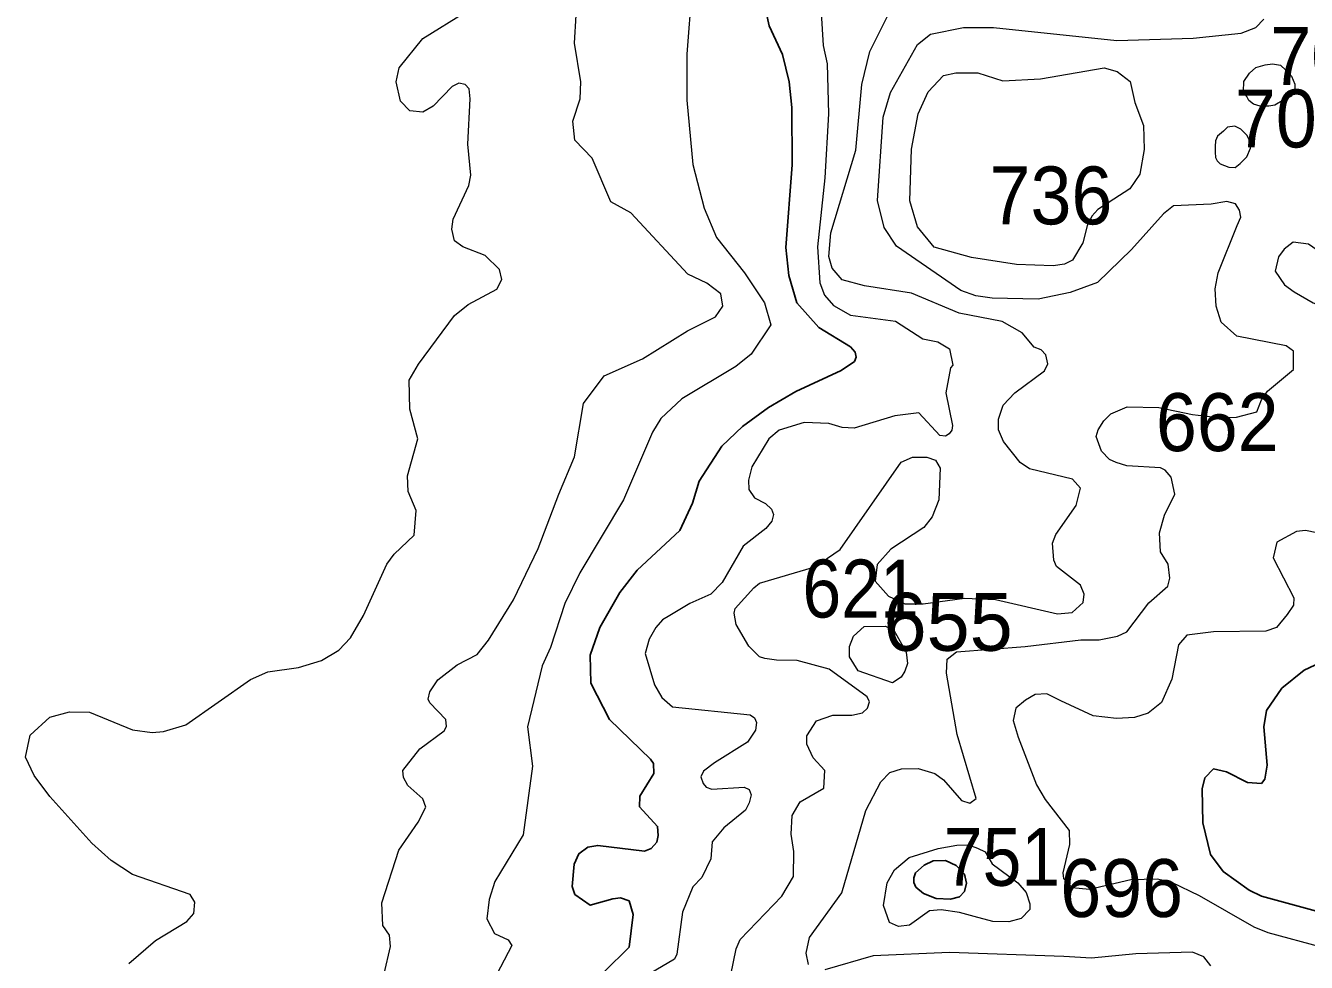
# Model space of a CAD drawing. Extents: x 499.9 to 555.3, y 9281.5 to 9336.8.
# Drawn here: x 537.076 to 540.616, y 9287.136 to 9289.724 of the extents above; entities that cross this region are included whole.
import ezdxf

# ---------------------------------------------------------------- set-up
doc = ezdxf.new("R2010")
doc.units = 0
doc.header["$LTSCALE"] = 0.064
doc.layers.add('1', color=7, linetype='Continuous', lineweight=25)
doc.layers.add('2', color=7, linetype='Continuous', lineweight=13)
doc.layers.add('21', color=7, linetype='Continuous')

msp = doc.modelspace()

# ---------------------------------------------------------------- linework, layer by layer
at = {"layer": '1'}
for points in [[(539.1142, 9289.7992), (539.1309, 9289.7229), (539.1682, 9289.6435), (539.1868, 9289.5684), (539.1943, 9289.4975), (539.1947, 9289.3393), (539.1773, 9289.1109), (539.1854, 9289.0337), (539.2081, 9288.9575), (539.2687, 9288.8893), (539.3559, 9288.836), (539.3689, 9288.8216), (539.3713, 9288.8081), (539.3673, 9288.7959), (539.3299, 9288.7704), (539.2048, 9288.7125), (539.1295, 9288.6684), (539.0579, 9288.6159), (539.0006, 9288.5618), (538.9382, 9288.4655), (538.9193, 9288.4043), (538.8846, 9288.3287), (538.7661, 9288.2189), (538.7189, 9288.1575), (538.6636, 9288.0612), (538.6362, 9287.9841), (538.6381, 9287.907), (538.6899, 9287.8065), (538.8029, 9287.6974), (538.8118, 9287.6849), (538.8123, 9287.6579), (538.7735, 9287.5947), (538.773, 9287.5656), (538.8227, 9287.5111), (538.824, 9287.4858), (538.8205, 9287.4677), (538.8047, 9287.4503), (538.7863, 9287.4433), (538.6576, 9287.4586), (538.6298, 9287.4538), (538.6056, 9287.4359), (538.5926, 9287.4069), (538.5869, 9287.3451), (538.5942, 9287.3234), (538.637, 9287.2937), (538.6992, 9287.3116), (538.72, 9287.3144), (538.7439, 9287.3055), (538.7552, 9287.2678), (538.744, 9287.1773), (538.6749, 9287.1093)], [(540.6821, 9287.9773), (540.6097, 9287.9425), (540.5477, 9287.8931), (540.5059, 9287.8314), (540.4983, 9287.7865), (540.5078, 9287.6809), (540.5007, 9287.6417), (540.4914, 9287.6298), (540.4529, 9287.6328), (540.3947, 9287.6624), (540.359, 9287.6701), (540.3351, 9287.6454), (540.328, 9287.6155), (540.3295, 9287.5209), (540.3512, 9287.4333), (540.3863, 9287.3863), (540.4577, 9287.3353), (540.4919, 9287.3189), (540.7655, 9287.2438)]]:
    msp.add_lwpolyline(points, dxfattribs=at)
msp.add_lwpolyline([(539.5366, 9287.3431), (539.5574, 9287.326), (539.593, 9287.3119), (539.6324, 9287.3104), (539.6576, 9287.3163), (539.671, 9287.3319), (539.6769, 9287.3542), (539.671, 9287.3794), (539.648, 9287.4032), (539.6183, 9287.4173), (539.5848, 9287.4158), (539.5596, 9287.404), (539.5358, 9287.3832), (539.5306, 9287.369), (539.5314, 9287.3564)], close=True, dxfattribs=at)
at = {"layer": '2'}
for points in [[(538.9179, 9289.8247), (538.9034, 9289.6449), (538.9035, 9289.5176), (538.9199, 9289.34), (538.9513, 9289.2192), (538.9855, 9289.138), (539.0631, 9289.0403), (539.1179, 9288.9581), (539.1357, 9288.8967), (539.0813, 9288.8163), (539.0388, 9288.7821), (538.8898, 9288.6927), (538.8319, 9288.6381), (538.8092, 9288.6009), (538.7283, 9288.4139), (538.6084, 9288.2117), (538.5661, 9288.1273), (538.5267, 9288.0057), (538.5038, 9287.9547), (538.4631, 9287.7868), (538.4769, 9287.6775), (538.4516, 9287.4883), (538.3727, 9287.3587), (538.357, 9287.309), (538.3512, 9287.2564), (538.3721, 9287.2155), (538.4098, 9287.1977), (538.4205, 9287.1826), (538.3365, 9287.022)], [(539.2717, 9289.8054), (539.2806, 9289.6687), (539.2918, 9289.6184), (539.2949, 9289.4801), (539.2855, 9289.3027), (539.2645, 9289.1126), (539.2715, 9289.0133), (539.2841, 9288.979), (539.3091, 9288.9505), (539.3562, 9288.9236), (539.4803, 9288.9067), (539.5559, 9288.8582), (539.5974, 9288.8497), (539.63, 9288.8311), (539.6387, 9288.786), (539.6321, 9288.7784), (539.6197, 9288.7089), (539.6381, 9288.6193), (539.6359, 9288.6064), (539.6289, 9288.5957), (539.6182, 9288.5893), (539.6033, 9288.591), (539.5445, 9288.654), (539.4781, 9288.6457), (539.3665, 9288.6112), (539.3325, 9288.613), (539.2965, 9288.624), (539.2281, 9288.6269), (539.1592, 9288.6059), (539.1301, 9288.5823), (539.0829, 9288.5044), (539.0739, 9288.468), (539.0754, 9288.4416), (539.0906, 9288.4187), (539.1212, 9288.4031), (539.1377, 9288.3873), (539.143, 9288.3726), (539.1387, 9288.355), (539.1217, 9288.3347), (539.0591, 9288.2857), (539.0009, 9288.1853), (538.9704, 9288.1529), (538.9124, 9288.1267), (538.8564, 9288.0944), (538.8364, 9288.0816), (538.8181, 9288.0611), (538.7992, 9288.0289), (538.7881, 9287.9889), (538.8141, 9287.9027), (538.835, 9287.8672), (538.8642, 9287.8416), (539.0784, 9287.8194), (539.0907, 9287.8113), (539.0965, 9287.7987), (539.0938, 9287.7773), (539.0709, 9287.7444), (538.9805, 9287.6868), (538.9501, 9287.6639), (538.942, 9287.6487), (538.9484, 9287.6294)], [(538.1386, 9288.6641), (538.1364, 9288.744), (538.1622, 9288.7884), (538.2616, 9288.9224), (538.2997, 9288.9529), (538.3787, 9288.9956), (538.3923, 9289.0225), (538.3863, 9289.0496), (538.3463, 9289.0885), (538.2844, 9289.1126), (538.2618, 9289.129), (538.2543, 9289.1611), (538.2584, 9289.1892), (538.3014, 9289.2821), (538.3065, 9289.3107), (538.2987, 9289.3958), (538.3048, 9289.5215), (538.3018, 9289.5487), (538.2909, 9289.5611), (538.274, 9289.5648), (538.2553, 9289.5551), (538.2024, 9289.5008), (538.1738, 9289.4843), (538.1386, 9289.4885), (538.1128, 9289.5149), (538.1004, 9289.5681), (538.1084, 9289.607), (538.174, 9289.6882), (538.2931, 9289.7615)], [(538.0669, 9287.1041), (538.0852, 9287.1795), (538.0819, 9287.2105), (538.0633, 9287.2371), (538.0612, 9287.3002), (538.1077, 9287.4461), (538.1616, 9287.5226), (538.1822, 9287.5644), (538.174, 9287.5876), (538.1324, 9287.6241), (538.1209, 9287.646), (538.1193, 9287.6662), (538.1661, 9287.7257), (538.233, 9287.7754), (538.2394, 9287.7869), (538.2374, 9287.8069), (538.1939, 9287.8531), (538.1893, 9287.8629), (538.1939, 9287.883), (538.2158, 9287.9158), (538.269, 9287.9574), (538.3246, 9287.9863), (538.3559, 9288.0255), (538.4244, 9288.1369), (538.4925, 9288.2794), (538.5498, 9288.429), (538.5931, 9288.5324), (538.6181, 9288.6794), (538.6749, 9288.7561), (538.781, 9288.803), (538.9057, 9288.8804), (538.9829, 9288.9191), (539.0034, 9288.9486), (538.9981, 9288.9825), (538.9591, 9289.0121), (538.9061, 9289.0368), (538.7488, 9289.2066), (538.6937, 9289.2369), (538.6417, 9289.3575), (538.5942, 9289.4067), (538.5885, 9289.4593), (538.6089, 9289.5216), (538.6104, 9289.5687), (538.5931, 9289.6751), (538.598, 9289.7522)], [(539.8918, 9288.77), (539.901, 9288.7895), (539.896, 9288.8137), (539.8831, 9288.8277), (539.8633, 9288.8353), (539.8302, 9288.8748), (539.7751, 9288.9058), (539.6561, 9288.9296), (539.5249, 9288.9848), (539.3944, 9289.0046), (539.3326, 9289.0212), (539.3052, 9289.0538), (539.2964, 9289.086), (539.3016, 9289.1512), (539.3709, 9289.3796), (539.3874, 9289.5605), (539.4096, 9289.652), (539.4574, 9289.7475)], [(540.4248, 9289.1715), (540.4348, 9289.1948), (540.4309, 9289.214), (540.4201, 9289.2316), (540.3958, 9289.2381), (540.3531, 9289.2301), (540.2486, 9289.2261), (540.2205, 9289.204), (540.1327, 9289.1051), (540.0381, 9289.014), (539.9631, 9288.9862), (539.8744, 9288.9681), (539.7478, 9288.9708), (539.7025, 9288.9773), (539.6611, 9288.9919), (539.4828, 9289.1144), (539.449, 9289.1661), (539.431, 9289.2404), (539.4458, 9289.4703), (539.4669, 9289.5388), (539.5408, 9289.6716), (539.577, 9289.7002), (539.6682, 9289.7188), (539.751, 9289.7187), (540.0921, 9289.6823), (540.3033, 9289.6886), (540.4352, 9289.7032), (540.4762, 9289.7184), (540.4981, 9289.7418)], [(540.4236, 9288.8654), (540.3803, 9288.9048), (540.3662, 9288.9486), (540.3635, 9288.9965), (540.372, 9289.041), (540.4248, 9289.1715)], [(539.2403, 9287.1301), (539.233, 9287.1612), (539.2423, 9287.204), (539.3318, 9287.3282), (539.3982, 9287.5551), (539.4399, 9287.634), (539.4647, 9287.6605), (539.4967, 9287.6706), (539.5431, 9287.6713), (539.589, 9287.6572), (539.6133, 9287.6403), (539.6628, 9287.5832), (539.6853, 9287.5753), (539.7028, 9287.5885), (539.6507, 9287.765), (539.6209, 9287.9346), (539.623, 9287.9734), (539.6488, 9287.9939), (539.8385, 9288.0079), (539.9922, 9288.027), (540.043, 9288.0271), (540.0939, 9288.0368), (540.1197, 9288.0484), (540.18, 9288.1288), (540.2327, 9288.1749), (540.2385, 9288.1973), (540.234, 9288.2357), (540.2123, 9288.2699), (540.2102, 9288.3221), (540.2238, 9288.3708), (540.2527, 9288.4288), (540.2422, 9288.476), (540.2256, 9288.4957), (540.2126, 9288.5022), (540.1197, 9288.5073), (540.09, 9288.5167), (540.072, 9288.525), (540.0497, 9288.5476), (540.0353, 9288.5888), (540.0405, 9288.607), (540.0559, 9288.6313), (540.075, 9288.6507), (540.1202, 9288.67), (540.2078, 9288.6685), (540.301, 9288.6488), (540.3797, 9288.6399), (540.4226, 9288.6416), (540.4793, 9288.6566), (540.4916, 9288.69), (540.5079, 9288.7134), (540.5802, 9288.7733), (540.5805, 9288.8242), (540.5601, 9288.8385), (540.4236, 9288.8654)], [(539.7789, 9288.5744), (539.7648, 9288.6073), (539.7647, 9288.6366), (539.7783, 9288.6753), (539.8103, 9288.7094), (539.8918, 9288.77)], [(538.1502, 9288.3162), (538.1554, 9288.3838), (538.1333, 9288.4362), (538.1316, 9288.48), (538.1599, 9288.5824), (538.1386, 9288.6641)], [(539.0118, 9287.034), (539.0403, 9287.1734), (539.051, 9287.199), (539.1659, 9287.3188), (539.1983, 9287.3728), (539.1994, 9287.4421), (539.1917, 9287.49), (539.195, 9287.5415), (539.2172, 9287.5796), (539.2821, 9287.6173), (539.285, 9287.6656), (539.2529, 9287.7009), (539.235, 9287.7383), (539.235, 9287.7618), (539.2618, 9287.8032), (539.307, 9287.8182), (539.3593, 9287.8189), (539.3889, 9287.825), (539.403, 9287.8375), (539.4081, 9287.8551), (539.4023, 9287.8693), (539.2971, 9287.9459), (539.2083, 9287.9697), (539.1512, 9287.971), (539.1193, 9287.975), (539.1043, 9287.9797), (539.0752, 9288.0088), (539.0399, 9288.0693), (539.0349, 9288.1003), (539.0374, 9288.1129), (539.0886, 9288.17), (539.1048, 9288.1831), (539.2577, 9288.2286), (539.3273, 9288.276), (539.4962, 9288.5176), (539.5274, 9288.5313), (539.5669, 9288.5315), (539.5908, 9288.5233), (539.6034, 9288.5012), (539.6004, 9288.4133), (539.5813, 9288.3661), (539.5587, 9288.3374), (539.4674, 9288.2773), (539.4296, 9288.2351), (539.4243, 9288.1885), (539.4612, 9288.1472), (539.5058, 9288.1258), (539.5567, 9288.1258), (539.6706, 9288.1416), (539.7565, 9288.1384), (539.9277, 9288.0987), (539.9688, 9288.1023), (539.9994, 9288.1299), (540.0014, 9288.1528), (539.9914, 9288.1775), (539.9256, 9288.2293), (539.9179, 9288.247), (539.9142, 9288.2938), (539.9236, 9288.3176), (539.9792, 9288.3979), (539.9917, 9288.4454), (539.9696, 9288.4709), (539.8504, 9288.4993), (539.8248, 9288.5163), (539.7789, 9288.5744)], [(537.3613, 9287.1326), (537.4354, 9287.1963), (537.5217, 9287.2487), (537.541, 9287.2703), (537.5441, 9287.3023), (537.5312, 9287.3234), (537.3718, 9287.378), (537.3126, 9287.4173), (537.2598, 9287.4649), (537.1432, 9287.5942), (537.0999, 9287.6521), (537.0764, 9287.7022), (537.0889, 9287.7637), (537.1434, 9287.8128), (537.1981, 9287.8281), (537.253, 9287.8266), (537.3715, 9287.7783), (537.4258, 9287.7709), (537.4574, 9287.7731), (537.5188, 9287.7916), (537.6977, 9287.9174), (537.7456, 9287.938), (537.8307, 9287.9507), (537.8939, 9287.9695), (537.9421, 9287.9984), (537.9738, 9288.0319), (538.0097, 9288.0938), (538.0743, 9288.2355), (538.0945, 9288.2638), (538.1502, 9288.3162)], [(540.6447, 9288.3222), (540.6136, 9288.3292), (540.5889, 9288.3264), (540.5338, 9288.2961), (540.5241, 9288.2532), (540.5808, 9288.1425), (540.5806, 9288.1226), (540.5628, 9288.0968), (540.5328, 9288.0608), (540.5038, 9288.0511), (540.3594, 9288.0492), (540.2851, 9288.0394), (540.2627, 9288.0132), (540.2437, 9287.918), (540.2153, 9287.8532), (540.1789, 9287.8239), (540.1412, 9287.812), (540.0912, 9287.8091), (540.0262, 9287.8165), (539.9374, 9287.8585), (539.8981, 9287.8774), (539.8664, 9287.8761), (539.84, 9287.8601), (539.813, 9287.8377), (539.8055, 9287.8036), (539.8189, 9287.7574), (539.8704, 9287.6262), (539.8939, 9287.5856), (539.9599, 9287.5001), (539.9615, 9287.4613), (539.9429, 9287.3834), (539.9449, 9287.3677), (539.9689, 9287.3421), (540.0161, 9287.3383), (540.1307, 9287.365), (540.2046, 9287.3665), (540.2428, 9287.3571), (540.3192, 9287.3207), (540.4702, 9287.2341), (540.5094, 9287.2181), (540.6598, 9287.1773)], [(538.9484, 9287.6294), (538.9567, 9287.6197), (538.9727, 9287.6145), (539.0619, 9287.6195), (539.0762, 9287.6134), (539.0811, 9287.5984)], [(539.0811, 9287.5984), (539.0755, 9287.5765), (539.0655, 9287.556), (539.006, 9287.5071), (538.9741, 9287.469), (538.9696, 9287.4213), (538.9451, 9287.3705), (538.9207, 9287.3439), (538.8916, 9287.2741), (538.8763, 9287.1581), (538.8696, 9287.1444), (538.7393, 9287.0685)], [(540.3518, 9287.1264), (540.3322, 9287.1514), (540.3015, 9287.1642), (540.1449, 9287.1596), (540.0219, 9287.147), (539.9458, 9287.1517), (539.6298, 9287.1629), (539.4186, 9287.1539), (539.2853, 9287.1148)]]:
    msp.add_lwpolyline(points, dxfattribs=at)
for points in [[(540.4431, 9289.5692), (540.4585, 9289.5919), (540.476, 9289.6083), (540.5017, 9289.6155), (540.5223, 9289.6176), (540.5439, 9289.6145), (540.5594, 9289.6001), (540.5748, 9289.5836), (540.584, 9289.562), (540.584, 9289.5476), (540.5748, 9289.5291), (540.5532, 9289.5188), (540.5285, 9289.5034), (540.512, 9289.5013), (540.4884, 9289.5013), (540.4699, 9289.5065), (540.4565, 9289.5168), (540.4513, 9289.5281), (540.4421, 9289.5415)], [(539.8151, 9289.0634), (539.6907, 9289.0826), (539.5869, 9289.1112), (539.5407, 9289.1678), (539.5199, 9289.2391), (539.5242, 9289.3822), (539.5433, 9289.4801), (539.5707, 9289.5411), (539.6129, 9289.5861), (539.6468, 9289.5932), (539.7081, 9289.5931), (539.7772, 9289.5713), (539.8808, 9289.5768), (540.0572, 9289.6073), (540.0926, 9289.597), (540.1288, 9289.569), (540.1419, 9289.5113), (540.1655, 9289.4476), (540.1671, 9289.3814), (540.1552, 9289.3132), (540.1281, 9289.2729), (540.0395, 9289.2152), (540.0229, 9289.1973), (540.0101, 9289.1707), (539.9982, 9289.1238), (539.9691, 9289.0756), (539.9475, 9289.0649), (539.9157, 9289.06)], [(540.3772, 9289.3419), (540.4019, 9289.3327), (540.4194, 9289.3316), (540.4328, 9289.3429), (540.4513, 9289.3615), (540.4616, 9289.3851), (540.4605, 9289.4026), (540.4523, 9289.4201), (540.4348, 9289.4376), (540.4183, 9289.4458), (540.3978, 9289.4427), (540.3865, 9289.4324), (540.37, 9289.418), (540.3649, 9289.4057), (540.3638, 9289.3892), (540.3638, 9289.3738), (540.3649, 9289.3594), (540.369, 9289.3501)], [(540.5819, 9288.9879), (540.6341, 9288.9578), (540.6976, 9288.9336), (540.8099, 9288.9412), (540.8517, 9288.9609), (540.8635, 9288.9899), (540.8488, 9289.0205), (540.8016, 9289.0459), (540.6905, 9289.0718), (540.6213, 9289.1199), (540.5797, 9289.1249), (540.554, 9289.106), (540.5389, 9289.0851), (540.53, 9289.0452), (540.5556, 9289.0079)], [(539.472, 9287.9083), (539.3774, 9287.9415), (539.3533, 9287.9796), (539.3535, 9288.0081), (539.3646, 9288.0373), (539.3942, 9288.0639), (539.4524, 9288.0643), (539.4753, 9288.0533), (539.5099, 9287.9923), (539.5138, 9287.9616), (539.5065, 9287.9405), (539.4962, 9287.9236)], [(539.6973, 9287.262), (539.657, 9287.2731), (539.6067, 9287.2804), (539.5746, 9287.2784), (539.5187, 9287.2387), (539.4888, 9287.2351), (539.4633, 9287.2461), (539.4475, 9287.2927), (539.4572, 9287.3552), (539.4778, 9287.3915), (539.5183, 9287.4256), (539.5978, 9287.4499), (539.6499, 9287.4594), (539.6818, 9287.4601), (539.7068, 9287.4515), (539.7277, 9287.4411), (539.7475, 9287.4078), (539.8185, 9287.3553), (539.8411, 9287.3283), (539.8515, 9287.2973), (539.852, 9287.282), (539.828, 9287.257), (539.7932, 9287.2476), (539.7492, 9287.2486)]]:
    msp.add_lwpolyline(points, close=True, dxfattribs=at)

# ---------------------------------------------------------------- texts
at = {"layer": '21'}
for s, width, p in [('704', 0.95, (540.5161, 9289.5595)), ('706', 0.95, (540.4184, 9289.3871)), ('736', 0.95, (539.7404, 9289.1745)), ('662', 0.95, (540.2, 9288.5481)), ('621', 0.9, (539.2232, 9288.0884)), ('751', 0.9, (539.6139, 9287.3472)), ('696', 0.95, (539.9357, 9287.261))]:
    msp.add_text(s, height=0.16, dxfattribs=dict(at, width=width)).set_placement(p)
msp.add_text('655', height=0.16, dxfattribs=at).set_placement((539.4473, 9287.9965))

doc.saveas('drawing.dxf')
